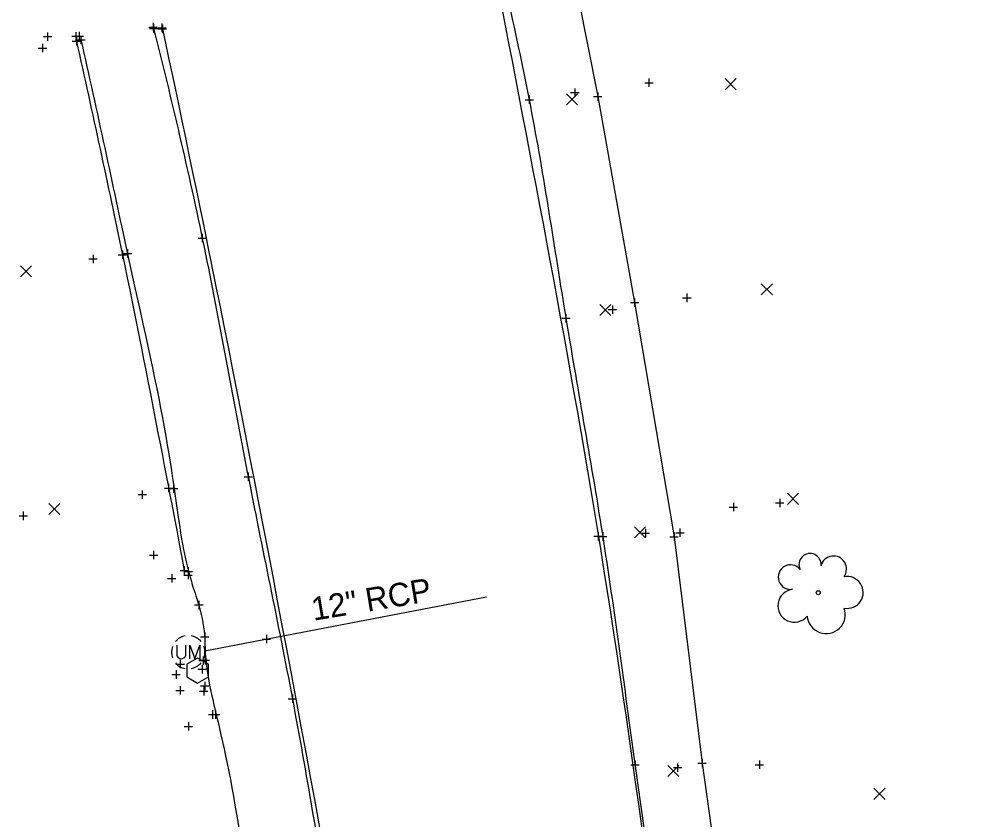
# Model space of a CAD drawing. Extents: x 2188719 to 2189819, y 654569 to 659504.
# Drawn here: x 2189670.8 to 2189785.2, y 658253.3 to 658349 of the extents above; entities that cross this region are included whole.
import ezdxf

# ---------------------------------------------------------------- set-up
doc = ezdxf.new("R2010")
doc.units = 0
for name, color, linetype in [('DR_X_Elev_Flow', 7, 'Continuous'), ('DR_X_Storm_Sewer', 7, 'Continuous'), ('DR_X_Text', 7, 'Continuous'), ('PM_X_Edge_Line', 7, 'Continuous'), ('PM_X_Transverse_Line', 7, 'Continuous'), ('PV_X_Curb', 7, 'Continuous'), ('PV_X_EOP', 7, 'Continuous'), ('PV_X_Shoulder', 7, 'Continuous'), ('RD_X_Cells', 7, 'Continuous'), ('SV_X_Random_Point', 7, 'Continuous'), ('SV_X_Shot_Marker', 7, 'Continuous'), ('UT_X_Unknown_Cells', 7, 'Continuous'), ('VG_X_Cells', 7, 'Continuous')]:
    doc.layers.add(name, color=color, linetype=linetype)

msp = doc.modelspace()

# ---------------------------------------------------------------- linework, layer by layer
at = {"layer": 'DR_X_Elev_Flow'}
for p, q in [((2189700.35, 658275.38), (2189700.35, 658274.38)), ((2189699.85, 658274.88), (2189700.85, 658274.88)), ((2189700.35, 658274.88), (2189700.35, 658274.88))]:
    msp.add_line(p, q, dxfattribs=at)
at = {"layer": 'DR_X_Storm_Sewer'}
msp.add_line((2189693, 658273.47), (2189726.63, 658279.94), dxfattribs=at)
at = {"layer": 'PM_X_Edge_Line'}
msp.add_open_spline([(2189715.92, 658416.15), (2189719.55, 658398.42), (2189727.31, 658355.37), (2189741.15, 658285.79), (2189752.08, 658199.49), (2189764.73, 658083.92), (2189776.67, 657949.48), (2189785.57, 657773.05), (2189784.87, 657651.45), (2189781.91, 657575.63)], degree=3, dxfattribs=at)
at = {"layer": 'PM_X_Transverse_Line'}
msp.add_open_spline([(2189687.91, 658347.82), (2189695.6, 658312.27), (2189724.53, 658165.17), (2189751.08, 657933.72), (2189754.2, 657738.17), (2189752.07, 657655.83)], degree=3, dxfattribs=at)
at = {"layer": 'PV_X_Curb'}
msp.add_open_spline([(2189677.65, 658346.34), (2189679.54, 658337.85), (2189683.37, 658320.07), (2189687.52, 658298.95), (2189689.92, 658286.35), (2189690.53, 658283.06)], degree=3, dxfattribs=at)
at = {"layer": 'PV_X_EOP'}
for points in [[(2189715.65, 658416.09), (2189717.36, 658407.13), (2189721.67, 658389.5), (2189726.25, 658363.76), (2189732.27, 658338.61), (2189735.95, 658313.21), (2189740.83, 658286.81), (2189744.4, 658258.95), (2189748.43, 658232.12), (2189751.61, 658205.72), (2189755.02, 658180.62), (2189757.39, 658155.27), (2189760.52, 658129.99), (2189762.73, 658103.87), (2189765.52, 658076.79), (2189767.84, 658049.53), (2189770.28, 658023.15), (2189773.03, 657997.24), (2189774.6, 657969.67), (2189777.01, 657941.26), (2189778.8, 657911.99), (2189780.69, 657884.09), (2189781.4, 657856.58), (2189782.11, 657829.65), (2189783.53, 657801.33), (2189783.56, 657772.66), (2189783.96, 657743.23), (2189783.95, 657715.3), (2189783.44, 657687.6), (2189783.88, 657660.21), (2189783.01, 657632.25), (2189782.93, 657604.05), (2189782.64, 657585.12), (2189782.5, 657575.65)], [(2189686.87, 658347.88), (2189688.95, 658339.56), (2189693.17, 658321.78), (2189697.87, 658294.9), (2189703.7, 658267.62), (2189707.98, 658241.03), (2189713.11, 658215.13), (2189716.61, 658188.45), (2189721.68, 658160.42), (2189724.61, 658131.33), (2189729.42, 658103.12), (2189732.17, 658074.94), (2189735.91, 658046.42), (2189738.42, 658016.97), (2189741.68, 657987.88), (2189743.15, 657958.86), (2189745.92, 657930.4), (2189747.37, 657902.49), (2189749.54, 657874.27), (2189750.21, 657845.72), (2189752.04, 657816.78), (2189752.93, 657788.08), (2189753.38, 657759.61), (2189754.01, 657732.65), (2189754.13, 657706.9), (2189754.02, 657681.8), (2189752.87, 657664.76), (2189752.08, 657656.03)]]:
    msp.add_open_spline(points, degree=3, dxfattribs=at)
at = {"layer": 'PV_X_Shoulder'}
for p, q in [((2189736, 658359.7), (2189739.92, 658339.73)), ((2189739.92, 658339.73), (2189744.33, 658315.11)), ((2189744.33, 658315.11), (2189749.04, 658287.11)), ((2189749.04, 658287.11), (2189752.4, 658260.05)), ((2189752.4, 658260.05), (2189756.49, 658230.8))]:
    msp.add_line(p, q, dxfattribs=at)
msp.add_open_spline([(2189678.17, 658346.51), (2189680.12, 658338.02), (2189683.83, 658320.14), (2189688.68, 658299.1), (2189690.22, 658284.76), (2189692.33, 658279.09), (2189693.11, 658275.51), (2189692.87, 658271.06), (2189696.13, 658259.46), (2189698.82, 658239.7), (2189703.41, 658214.08), (2189707.68, 658187.35), (2189711.85, 658159.43), (2189715.66, 658130.84), (2189719.89, 658102.92), (2189722.84, 658074.64), (2189726.21, 658045.96), (2189729.3, 658016.08), (2189731.79, 657986.57), (2189734.56, 657957.49), (2189736.24, 657929.57), (2189738.31, 657902.49), (2189739.34, 657874.4), (2189741.63, 657845.81), (2189742.72, 657816.8), (2189743.78, 657788), (2189744.99, 657759.47), (2189745.29, 657733.99), (2189744.96, 657716.97), (2189745.15, 657707.52), (2189744.91, 657697.88), (2189745.01, 657680.84), (2189744.6, 657665.71), (2189744.35, 657657.17)], degree=3, dxfattribs=at)
at = {"layer": 'RD_X_Cells'}
msp.add_lwpolyline([(2189690.82, 658270.36), (2189692.12, 658269.61), (2189693.41, 658270.36), (2189693.41, 658271.86), (2189692.12, 658272.61), (2189690.82, 658271.86), (2189690.82, 658270.36)], dxfattribs=at)
at = {"layer": 'SV_X_Random_Point'}
for p, q in [((2189755.15, 658340.55), (2189756.48, 658341.88)), ((2189755.15, 658341.88), (2189756.48, 658340.55)), ((2189736.18, 658338.73), (2189737.51, 658340.07)), ((2189736.18, 658340.07), (2189737.51, 658338.73)), ((2189670.95, 658318.17), (2189672.28, 658319.51)), ((2189670.95, 658319.51), (2189672.28, 658318.17)), ((2189759.47, 658316.01), (2189760.8, 658317.35)), ((2189759.47, 658317.35), (2189760.8, 658316.01)), ((2189740.17, 658313.55), (2189741.5, 658314.88)), ((2189740.17, 658314.88), (2189741.5, 658313.55)), ((2189762.58, 658290.98), (2189763.91, 658292.31)), ((2189762.58, 658292.31), (2189763.91, 658290.98)), ((2189674.35, 658289.76), (2189675.68, 658291.09)), ((2189674.35, 658291.09), (2189675.68, 658289.76)), ((2189744.32, 658286.96), (2189745.65, 658288.29)), ((2189744.32, 658288.29), (2189745.65, 658286.96)), ((2189748.29, 658258.43), (2189749.63, 658259.76)), ((2189748.29, 658259.76), (2189749.63, 658258.43)), ((2189772.92, 658255.7), (2189774.26, 658257.04)), ((2189772.92, 658257.04), (2189774.26, 658255.7))]:
    msp.add_line(p, q, dxfattribs=at)
at = {"layer": 'SV_X_Shot_Marker'}
for p, q in [((2189686.8, 658348.54), (2189686.8, 658347.54)), ((2189686.87, 658348.38), (2189686.87, 658347.38)), ((2189686.87, 658348.38), (2189686.87, 658347.38)), ((2189687.85, 658348.46), (2189687.85, 658347.46)), ((2189687.91, 658348.32), (2189687.91, 658347.32)), ((2189687.91, 658348.32), (2189687.91, 658347.32)), ((2189674.2, 658347.4), (2189674.2, 658346.4)), ((2189677.58, 658347.45), (2189677.58, 658346.45)), ((2189677.98, 658347.46), (2189677.98, 658346.46)), ((2189686.3, 658348.04), (2189687.3, 658348.04)), ((2189686.37, 658347.88), (2189687.37, 658347.88)), ((2189686.37, 658347.88), (2189687.37, 658347.88)), ((2189686.8, 658348.04), (2189686.8, 658348.04)), ((2189686.87, 658347.88), (2189686.87, 658347.88)), ((2189686.87, 658347.88), (2189686.87, 658347.88)), ((2189687.35, 658347.96), (2189688.35, 658347.96)), ((2189687.41, 658347.82), (2189688.41, 658347.82)), ((2189687.41, 658347.82), (2189688.41, 658347.82)), ((2189687.85, 658347.96), (2189687.85, 658347.96)), ((2189687.91, 658347.82), (2189687.91, 658347.82)), ((2189687.91, 658347.82), (2189687.91, 658347.82)), ((2189673.59, 658346.02), (2189673.59, 658345.02)), ((2189673.7, 658346.9), (2189674.7, 658346.9)), ((2189674.2, 658346.9), (2189674.2, 658346.9)), ((2189677.08, 658346.95), (2189678.08, 658346.95)), ((2189677.15, 658346.34), (2189678.15, 658346.34)), ((2189677.15, 658346.34), (2189678.15, 658346.34)), ((2189677.48, 658346.96), (2189678.48, 658346.96)), ((2189677.58, 658346.95), (2189677.58, 658346.95)), ((2189677.65, 658346.84), (2189677.65, 658345.84)), ((2189677.65, 658346.84), (2189677.65, 658345.84)), ((2189677.65, 658346.34), (2189677.65, 658346.34)), ((2189677.65, 658346.34), (2189677.65, 658346.34)), ((2189677.67, 658346.51), (2189678.67, 658346.51)), ((2189677.67, 658346.51), (2189678.67, 658346.51)), ((2189677.98, 658346.96), (2189677.98, 658346.96)), ((2189678.17, 658347.01), (2189678.17, 658346.01)), ((2189678.17, 658347.01), (2189678.17, 658346.01)), ((2189678.17, 658346.51), (2189678.17, 658346.51)), ((2189678.17, 658346.51), (2189678.17, 658346.51)), ((2189673.09, 658345.52), (2189674.09, 658345.52)), ((2189673.59, 658345.52), (2189673.59, 658345.52)), ((2189745.55, 658341.39), (2189746.55, 658341.39)), ((2189746.05, 658341.89), (2189746.05, 658340.89)), ((2189746.05, 658341.39), (2189746.05, 658341.39)), ((2189736.69, 658340.21), (2189737.69, 658340.21)), ((2189737.19, 658340.71), (2189737.19, 658339.71)), ((2189737.19, 658340.21), (2189737.19, 658340.21)), ((2189739.92, 658340.23), (2189739.92, 658339.23)), ((2189731.24, 658339.35), (2189732.24, 658339.35)), ((2189731.74, 658339.85), (2189731.74, 658338.85)), ((2189731.74, 658339.35), (2189731.74, 658339.35)), ((2189739.42, 658339.73), (2189740.42, 658339.73)), ((2189739.92, 658339.73), (2189739.92, 658339.73)), ((2189692.68, 658323.31), (2189692.68, 658322.31)), ((2189692.18, 658322.81), (2189693.18, 658322.81)), ((2189692.68, 658322.81), (2189692.68, 658322.81)), ((2189679.63, 658320.82), (2189679.63, 658319.82)), ((2189682.63, 658320.82), (2189683.63, 658320.82)), ((2189683.13, 658321.32), (2189683.13, 658320.32)), ((2189683.13, 658320.82), (2189683.13, 658320.82)), ((2189683.25, 658320.98), (2189684.25, 658320.98)), ((2189683.75, 658321.48), (2189683.75, 658320.48)), ((2189683.75, 658320.98), (2189683.75, 658320.98)), ((2189679.13, 658320.32), (2189680.13, 658320.32)), ((2189679.63, 658320.32), (2189679.63, 658320.32)), ((2189750.57, 658316.17), (2189750.57, 658315.17)), ((2189743.83, 658315.11), (2189744.83, 658315.11)), ((2189744.33, 658315.61), (2189744.33, 658314.61)), ((2189744.33, 658315.11), (2189744.33, 658315.11)), ((2189750.07, 658315.67), (2189751.07, 658315.67)), ((2189750.57, 658315.67), (2189750.57, 658315.67)), ((2189741.18, 658314.27), (2189742.18, 658314.27)), ((2189741.68, 658314.77), (2189741.68, 658313.77)), ((2189741.68, 658314.27), (2189741.68, 658314.27)), ((2189735.62, 658313.22), (2189736.62, 658313.22)), ((2189736.12, 658313.72), (2189736.12, 658312.72)), ((2189736.12, 658313.22), (2189736.12, 658313.22)), ((2189698.17, 658294.78), (2189698.17, 658293.78)), ((2189688.66, 658293.43), (2189688.66, 658292.43)), ((2189689.24, 658293.37), (2189689.24, 658292.37)), ((2189697.67, 658294.28), (2189698.67, 658294.28)), ((2189698.17, 658294.28), (2189698.17, 658294.28)), ((2189685.01, 658292.15), (2189686.01, 658292.15)), ((2189685.51, 658292.65), (2189685.51, 658291.65)), ((2189685.51, 658292.15), (2189685.51, 658292.15)), ((2189688.16, 658292.93), (2189689.16, 658292.93)), ((2189688.66, 658292.93), (2189688.66, 658292.93)), ((2189688.74, 658292.87), (2189689.74, 658292.87)), ((2189689.24, 658292.87), (2189689.24, 658292.87)), ((2189756.13, 658291.15), (2189756.13, 658290.15)), ((2189761.17, 658291.15), (2189762.17, 658291.15)), ((2189761.67, 658291.65), (2189761.67, 658290.65)), ((2189761.67, 658291.15), (2189761.67, 658291.15)), ((2189671.3, 658290.11), (2189671.3, 658289.11)), ((2189755.63, 658290.65), (2189756.63, 658290.65)), ((2189756.13, 658290.65), (2189756.13, 658290.65)), ((2189670.8, 658289.61), (2189671.8, 658289.61)), ((2189671.3, 658289.61), (2189671.3, 658289.61)), ((2189739.98, 658287.67), (2189739.98, 658286.67)), ((2189740.52, 658287.64), (2189740.52, 658286.64)), ((2189745.13, 658287.54), (2189746.13, 658287.54)), ((2189745.63, 658288.04), (2189745.63, 658287.04)), ((2189745.63, 658287.54), (2189745.63, 658287.54)), ((2189749.04, 658287.61), (2189749.04, 658286.61)), ((2189749.24, 658287.58), (2189750.24, 658287.58)), ((2189749.74, 658288.08), (2189749.74, 658287.08)), ((2189749.74, 658287.58), (2189749.74, 658287.58)), ((2189739.48, 658287.17), (2189740.48, 658287.17)), ((2189739.98, 658287.17), (2189739.98, 658287.17)), ((2189740.02, 658287.14), (2189741.02, 658287.14)), ((2189740.52, 658287.14), (2189740.52, 658287.14)), ((2189748.54, 658287.11), (2189749.54, 658287.11)), ((2189749.04, 658287.11), (2189749.04, 658287.11)), ((2189686.86, 658285.42), (2189686.86, 658284.42)), ((2189686.36, 658284.92), (2189687.36, 658284.92)), ((2189686.86, 658284.92), (2189686.86, 658284.92)), ((2189690.03, 658283.06), (2189691.03, 658283.06)), ((2189690.53, 658283.56), (2189690.53, 658282.56)), ((2189690.53, 658283.06), (2189690.53, 658283.06)), ((2189690.98, 658283.03), (2189690.98, 658282.03)), ((2189691.01, 658283.44), (2189691.01, 658282.44)), ((2189688.53, 658282.13), (2189689.53, 658282.13)), ((2189689.03, 658282.63), (2189689.03, 658281.63)), ((2189689.03, 658282.13), (2189689.03, 658282.13)), ((2189690.48, 658282.53), (2189691.48, 658282.53)), ((2189690.51, 658282.94), (2189691.51, 658282.94)), ((2189690.98, 658282.53), (2189690.98, 658282.53)), ((2189691.01, 658282.94), (2189691.01, 658282.94)), ((2189691.77, 658278.96), (2189692.77, 658278.96)), ((2189692.27, 658279.46), (2189692.27, 658278.46)), ((2189692.27, 658278.96), (2189692.27, 658278.96)), ((2189692.48, 658275.15), (2189693.48, 658275.15)), ((2189692.98, 658275.65), (2189692.98, 658274.65)), ((2189692.98, 658275.15), (2189692.98, 658275.15)), ((2189692.78, 658272.81), (2189692.78, 658271.81)), ((2189693.03, 658272.84), (2189693.03, 658271.84)), ((2189689.54, 658271.88), (2189690.54, 658271.88)), ((2189690.04, 658272.38), (2189690.04, 658271.38)), ((2189690.04, 658271.88), (2189690.04, 658271.88)), ((2189692.28, 658272.31), (2189693.28, 658272.31)), ((2189692.53, 658272.34), (2189693.53, 658272.34)), ((2189692.65, 658271.76), (2189692.65, 658270.76)), ((2189692.78, 658272.31), (2189692.78, 658272.31)), ((2189693.03, 658272.34), (2189693.03, 658272.34)), ((2189689.05, 658270.64), (2189690.05, 658270.64)), ((2189689.55, 658271.14), (2189689.55, 658270.14)), ((2189689.55, 658270.64), (2189689.55, 658270.64)), ((2189692.15, 658271.26), (2189693.15, 658271.26)), ((2189692.65, 658271.26), (2189692.65, 658271.26)), ((2189690.03, 658269.24), (2189690.03, 658268.24)), ((2189692.48, 658269.27), (2189693.48, 658269.27)), ((2189692.98, 658269.77), (2189692.98, 658268.77)), ((2189692.98, 658269.27), (2189692.98, 658269.27)), ((2189689.53, 658268.74), (2189690.53, 658268.74)), ((2189690.03, 658268.74), (2189690.03, 658268.74)), ((2189692.36, 658268.65), (2189693.36, 658268.65)), ((2189692.86, 658269.15), (2189692.86, 658268.15)), ((2189692.86, 658268.65), (2189692.86, 658268.65)), ((2189703.44, 658268.24), (2189703.44, 658267.24)), ((2189702.94, 658267.74), (2189703.94, 658267.74)), ((2189703.44, 658267.74), (2189703.44, 658267.74)), ((2189693.42, 658265.86), (2189694.42, 658265.86)), ((2189693.77, 658265.86), (2189694.77, 658265.86)), ((2189693.92, 658266.36), (2189693.92, 658265.36)), ((2189693.92, 658265.86), (2189693.92, 658265.86)), ((2189694.27, 658266.36), (2189694.27, 658265.36)), ((2189694.27, 658265.86), (2189694.27, 658265.86)), ((2189691.02, 658264.93), (2189691.02, 658263.93)), ((2189690.52, 658264.43), (2189691.52, 658264.43)), ((2189691.02, 658264.43), (2189691.02, 658264.43)), ((2189744.38, 658260.35), (2189744.38, 658259.35)), ((2189752.4, 658260.55), (2189752.4, 658259.55)), ((2189759.25, 658260.36), (2189759.25, 658259.36)), ((2189743.88, 658259.85), (2189744.88, 658259.85)), ((2189744.38, 658259.85), (2189744.38, 658259.85)), ((2189748.96, 658259.51), (2189749.96, 658259.51)), ((2189749.46, 658260.01), (2189749.46, 658259.01)), ((2189749.46, 658259.51), (2189749.46, 658259.51)), ((2189751.9, 658260.05), (2189752.9, 658260.05)), ((2189752.4, 658260.05), (2189752.4, 658260.05)), ((2189758.75, 658259.86), (2189759.75, 658259.86)), ((2189759.25, 658259.86), (2189759.25, 658259.86))]:
    msp.add_line(p, q, dxfattribs=at)
at = {"layer": 'UT_X_Unknown_Cells'}
for p, q in [((2189689.65, 658274.13), (2189689.65, 658272.85)), ((2189690.66, 658274.13), (2189690.66, 658272.85)), ((2189691, 658273.31), (2189691, 658273.31))]:
    msp.add_line(p, q, dxfattribs=at)
msp.add_lwpolyline([(2189691.18, 658272.53), (2189691.18, 658274.13), (2189691.78, 658272.53), (2189692.37, 658274.13), (2189692.37, 658272.53)], dxfattribs=at)
for centre, radius, start, end in [((2189691, 658273.31), 2, 100.0806, 140.0721), ((2189691, 658273.31), 2, 40.0577, 80.1061), ((2189691, 658273.31), 2, 160.0169, 200.0392), ((2189691, 658273.31), 2, 340.0169, 20.0392), ((2189690.16, 658273.09), 0.557, 205.1924, 334.8076), ((2189691, 658273.31), 2, 220.0577, 260.0473), ((2189691, 658273.31), 2, 280.0114, 320.0264)]:
    msp.add_arc(centre, radius, start, end, dxfattribs=at)
at = {"layer": 'VG_X_Cells'}
msp.add_circle((2189766.27, 658280.42), 0.24, dxfattribs=at)
for centre, radius, start, end in [((2189765.29, 658283.79), 1.32, 354.0047, 205.9741), ((2189768.1, 658283.25), 1.55, 323.83, 165.0376), ((2189762.96, 658282.28), 1.47, 39.0625, 279.5412), ((2189769.73, 658280.45), 1.91, 259.1453, 101.4596), ((2189763.42, 658278.87), 1.97, 96.1722, 320.5737), ((2189767.22, 658277.81), 2.28, 184.9476, 19.4572)]:
    msp.add_arc(centre, radius, start, end, dxfattribs=at)

# ---------------------------------------------------------------- texts
at = {"layer": 'DR_X_Text'}
msp.add_text('12" RCP', height=2.8, rotation=9.5073, dxfattribs=at).set_placement((2189705.97, 658277.06))

doc.saveas('drawing.dxf')
